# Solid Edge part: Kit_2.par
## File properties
Sűrűség: 0,000 kg/m^3
Pontosság: 0,990
Author: bmolnar
Last saved by: bmolnar
Revision: 77
Username: bmolnar
Dokumentum tartalom típus: 0
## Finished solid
Body 1: solid body, 23 faces, 39 edges, 29 vertices.
  Faces by surface: plane 11, cylinder 8, cone 3, torus 1
  Edges by curve: circle 21, line 18
Bounding box of the edges (mm; curved faces can reach further): 35.700 x 35.450 x 3.850, from (-17.85, -16.85, 0.6) to (17.85, 18.6, 4.45).
Cylindrical faces by radius (mm): R1.25 x2, R2.25 x2, R11.5 x1, R15.9 x1, R16.85 x1, R17.85 x1
Conical faces (half-angle, radius in mm at the cone's reference point): 45 deg R11.25 x1, 45 deg R16.75 x2
Toroidal faces (ring radius, tube radius in mm): R11.9 r0.4 x1
Planar faces by outward normal: +z 2, -z 5, oblique 4
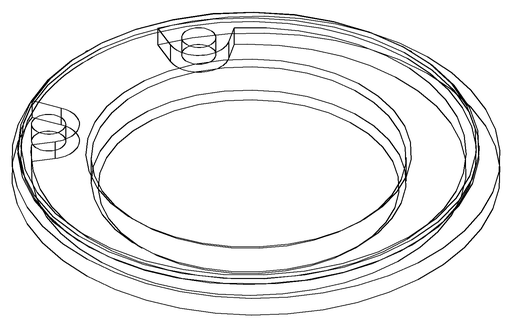
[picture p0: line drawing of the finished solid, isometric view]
